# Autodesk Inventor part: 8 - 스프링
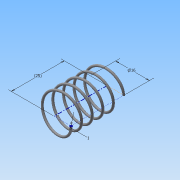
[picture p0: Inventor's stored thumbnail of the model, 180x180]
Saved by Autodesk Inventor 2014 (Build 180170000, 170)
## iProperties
Created: 2015-06
Part Number: 8 - 스프링
Material: 강철, 연강
Document SubType Name: Modeling
Designer: Administrator
Density: 1 g/cm^3
Appearance: 강철
Mass: 0.194641 g
Surface Area: 7.87024 cm^2
Volume: 0.194641 cm^3
Author: Administrator
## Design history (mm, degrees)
sketch "스케치1"
  geometry: L1 (0, 0)-(8, 0); L2 (8, 0)-(8, 14.5); L3 (8, 14.5)-(0, 14.5); L4 (0, 14.5)-(0, 0); C1 r 0.5 at (8, 0)
  constraints: 8 end point, 2 parallel, 1 centre point, 1 coincident, 1 horizontal, 1 perpendicular
  dimensions: "d0" = 14.5 distance between parallel lines of L1 L3 (derived); "d1" = 16 diameter of L2 L4; "d2" = 1 diameter of C1
feature "코일1" sketch "스케치1" pitch "d3" = 10; turns "d5" = 5; dims "d4" = 14.5 (= d0), "d6" = 0, angle "d7" = 90 deg, angle "d8" = 90 deg, "d9" = 0, "d10" = 0
node "작업 평면1"
sketch "스케치2"
  geometry: L1 (-8.5, 0)-(-7.5, 0) reference; 1 further point
  constraints: 1 horizontal alignment
extrude "돌출1" cut sketch "스케치2" distance "d12" = 10; taper "d13" = 0 deg
node "작업 평면2"
sketch "스케치3"
  geometry: L1 (-7.5, 0)-(-8.5, 0) reference; 1 further point
  constraints: 1 horizontal alignment
extrude "돌출2" cut sketch "스케치3" stored distance "d15" = 10; taper "d16" = 0 deg
node "솔리드1"
node "절단 모서리 투영1"
node "절단 모서리 투영2"
other parameters: "d11" = 0, "d14" = 14.5 (= d0)
